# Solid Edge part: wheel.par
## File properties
Title: Wheel
Subject: Wheel Assembly
Author: kiyo
Keywords: Wheel
Comments: Wheel 170 OD
Template: metric.par
Last saved by: edge
Revision: 29
Application: Solid Edge
File Size: 0
Number of Sheets: 0
Number of Objects: 0
Username: kiyo
文書内容のタイプ: 0
Material: Steel
Face Style: Steel
Fill Style: ANSI32(Steel)
Virtual Style: Machined steel
Coef. of Thermal Exp: 1.3e-05
Thermal Conductivity: 32.0
Specific Heat: 481.0
Modulus of Elasticity: 199947953000.0
Poisson's Ratio: 0.29
Yield Stress: 262000766.0
Ultimate Stress: 358527364.0
Elongation: 0.0
Category: Cast Machined Cylindrical
Manager: Brian Little
Company: Wheels R Us
Density: 7800
Accuracy: 0.99
Document Number: W-170
Revision: 1
Project Name: Trolley Wheel Assembly
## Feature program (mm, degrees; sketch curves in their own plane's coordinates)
sketch for "unnamed RevolvedProtrusion 1" plane through (0, 0, 0) normal (0, -1, 0) x-axis (1, 0, 0)
  line (-42.0228, -19.757) -> (-39.0228, -19.757)
  line (-39.0228, -19.757) -> (-39.0228, -18.757)
  line (-39.0228, -18.757) -> (-37.0228, -18.757)
  line (-37.0228, -18.757) -> (-37.0228, -19.757)
  line (-37.0228, -19.757) -> (-22.0228, -19.757)
  line (-22.0228, -19.757) -> (-22.0228, -18.757)
  line (-22.0228, -18.757) -> (-20.0228, -18.757)
  line (-20.0228, -18.757) -> (-20.0228, -19.757)
  line (-20.0228, -19.757) -> (-17.0228, -19.757)
  line (-17.0228, -19.757) -> (-17.0228, -12.757)
  line (-17.0228, -12.757) -> (-29.5228, -12.757)
  line (-29.5228, -12.757) -> (-29.5228, 15.243)
  line (-29.5228, 15.243) -> (-17.0228, 15.243)
  line (-17.0228, 15.243) -> (-17.0228, 25.243)
  line (-17.0228, 25.243) -> (-47.0228, 25.243)
  line (-47.0228, 25.243) -> (-47.0228, 40.243)
  line (-47.0228, 40.243) -> (-57.0228, 40.243)
  line (-57.0228, 40.243) -> (-57.0228, 15.243)
  line (-57.0228, 15.243) -> (-39.5228, 15.243)
  line (-39.5228, 15.243) -> (-39.5228, -12.757)
  line (-39.5228, -12.757) -> (-42.0228, -12.757)
  line (-42.0228, -12.757) -> (-42.0228, -19.757)
revolve "unnamed RevolvedProtrusion 1" add finite 360 deg about sketch line (-42.0228, -44.757) -> (-22.5184, -44.757)
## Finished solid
Body 1: solid body, 22 faces, 22 edges, 0 vertices.
  Faces by surface: cylinder 11, plane 11
  Edges by curve: circle 22
Bounding box of the edges (mm): 40.000 x 170.000 x 170.000, from (-57.0228, -85, -129.757) to (-17.0228, 85, 40.243).
Cylindrical faces by radius (mm): R25 x3, R26 x2, R32 x2, R60 x2, R70 x1, R85 x1
Planar faces by outward normal: +x 6, -x 5
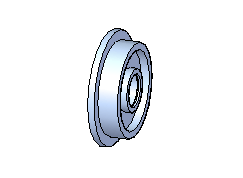
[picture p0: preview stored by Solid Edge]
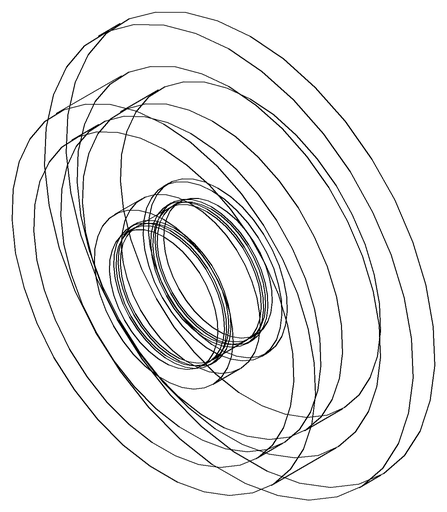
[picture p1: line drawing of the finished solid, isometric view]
